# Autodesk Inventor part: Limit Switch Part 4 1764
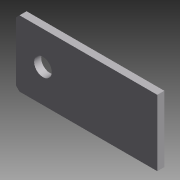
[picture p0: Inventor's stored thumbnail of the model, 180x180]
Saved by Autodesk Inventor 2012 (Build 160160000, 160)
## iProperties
Shininess: 0.0
Created: 2002-01
Part Number: Limit Switch Part 4 1764
Document SubType Name: Modeling
Density: 1 g/cm^3
Material: Default
Density: 0.0
Volumn: 0.0
Area: 0.0
PropertySet Name: Model Information
Control State: 0
Master: False
Checked Out: False
Author: Administrator
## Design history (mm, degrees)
node "Base1"
chamfer "Chamfer1" distance "d0" = 0.254; stored, may be unused: second distance "d1" = 3.175, angle "d2" = 45 deg
sketch "Sketch1"
  geometry: L1 (-9.906, 0)-(0, 0) reference; L2 (0, 4.75)-(-9.906, 4.75) reference; C1 r 0.635 at (-8.222, 2.375)
  constraints: 1 centre point
  dimensions: "d3" = 1.27 diameter of C1; "d4" = 4.7498 distance between parallel lines of L1 L2 (derived); "d5" = 2.3749 distance from line of L1 C1.centre (= 0.5 x d4)
extrude "Extrusion1" cut sketch "Sketch1" distance "d6" = 25.4; taper "d7" = 0 deg
body "Solid1"
